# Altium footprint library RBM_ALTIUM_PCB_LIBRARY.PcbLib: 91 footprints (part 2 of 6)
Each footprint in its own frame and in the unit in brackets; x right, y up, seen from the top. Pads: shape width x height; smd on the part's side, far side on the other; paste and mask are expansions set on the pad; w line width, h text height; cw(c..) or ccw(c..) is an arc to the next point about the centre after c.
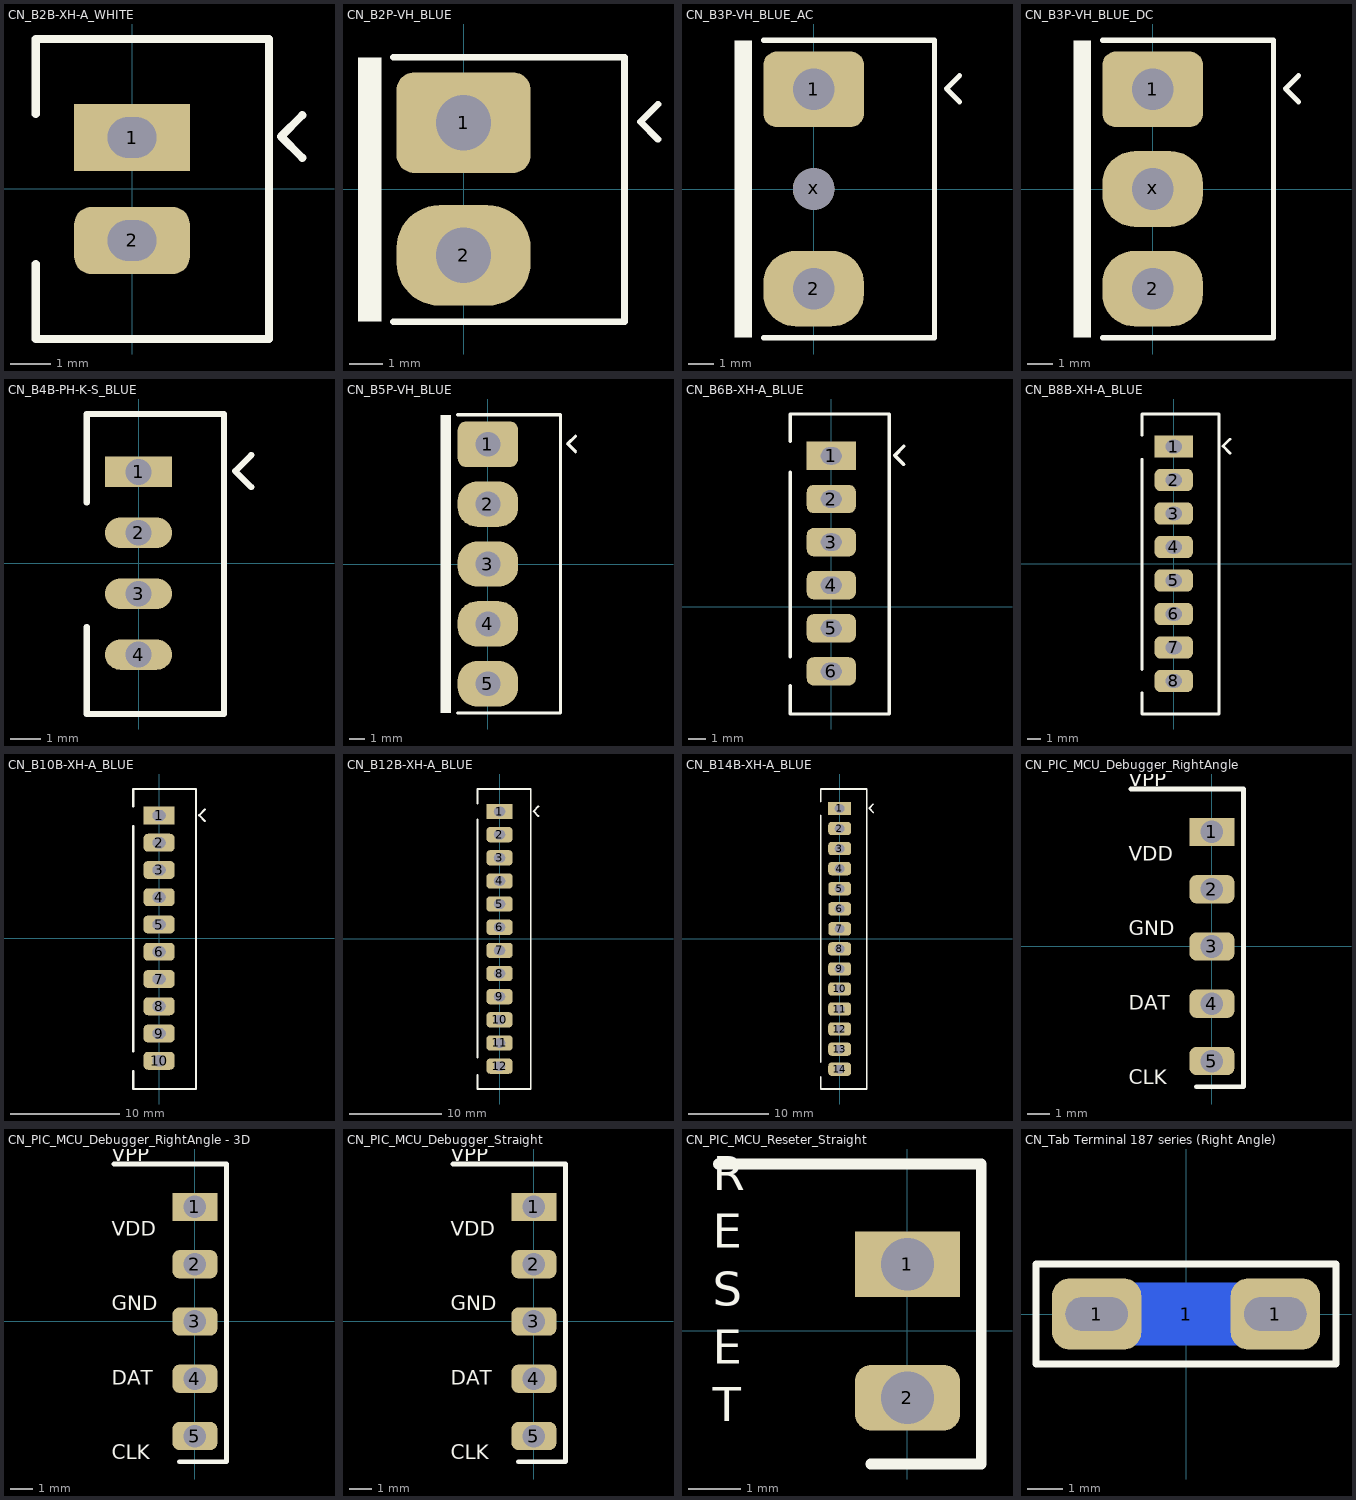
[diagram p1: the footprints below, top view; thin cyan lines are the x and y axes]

## CN_B2B-XH-A_WHITE [mm]
pads (2):
  rect 2.85x1.65 hole 1.2 slot 1 at 90 deg: 1(0,1.27)
  rrect50% 2.85x1.65 hole 1.2 slot 1 at 90 deg: 2(0,-1.27)
Top Overlay:
  lines w0.2: -2.375,-1.85 -2.375,-3.7 3.375,-3.7 3.375,3.7 -2.375,3.7 -2.375,1.85 ; 4.2,0.77 3.675,1.295 4.2,1.82
3D body "B2B-XH-A.STEP": height 7, standoff -3.4, extent -2.375,-3.7 3.375,3.7
3D body: height 7, standoff -3.5, extent -0.35,-1.615 0.35,-0.925
3D body: height 7, standoff -3.5, extent -0.35,0.925 0.35,1.615

## CN_B2P-VH_BLUE [mm] "3.96mm Pitch"
pads (2):
  rrect35% 4x3 hole 1.65: 1(0,1.98)
  rrect85% 4x3 hole 1.65: 2(0,-1.98)
Top Overlay:
  rectangle: -3.15,-3.96 -2.45,3.93
  lines w0.2: -2.1,-3.96 4.8,-3.96 4.8,3.93 -2.1,3.93 ; 5.8,1.48 5.275,2.005 5.8,2.53
3D body "B2P-VH.STEP": height 10.9, standoff -3.7, extent -3.75,-3.96 4.75,3.9

## CN_B3P-VH_BLUE_AC [mm] "3.96mm Pitch"
pads (3):
  rrect35% 4x3 / inner rect 4x2 / far side rect 4x2 hole 1.65: 1(0,3.96)
  rrect85% 4x3 hole 1.65: 2(0,-3.96)
  round 1.65 hole 1.65 unplated: x(0,0)
Top Overlay:
  rectangle: -3.15,-5.91 -2.45,5.91
  lines w0.2: -2,-5.91 4.8,-5.91 4.8,5.91 -2,5.91 ; 5.8,3.46 5.275,3.985 5.8,4.51
3D body "B3P-VH.STEP": height 10.9, standoff -3.7, extent -3.7,-5.91 4.8,5.91

## CN_B3P-VH_BLUE_DC [mm] "3.96mm Pitch"
pads (3):
  rrect35% 4x3 / inner rect 4x2 / far side rect 4x2 hole 1.65: 1(0,3.96)
  rrect85% 4x3 hole 1.65: 2(0,-3.96) x(0,0)
Top Overlay:
  rectangle: -3.15,-5.91 -2.45,5.91
  lines w0.2: -2,-5.91 4.8,-5.91 4.8,5.91 -2,5.91 ; 5.8,3.46 5.275,3.985 5.8,4.51
3D body "B3P-VH.STEP": height 10.9, standoff -3.7, extent -3.7,-5.91 4.8,5.91

## CN_B4B-PH-K-S_BLUE [mm] "Top Entry Header 2mm pitch 1X4pin  180° long"
pads (4):
  rect 2.2x1 hole 0.85: 1(0,3)
  oval 2.2x1 hole 0.85: 2(0,1) 3(0,-1) 4(0,-3)
Top Overlay:
  lines w0.2: -1.7,-2.1 -1.7,-4.95 2.8,-4.95 2.8,4.9 -1.7,4.9 -1.7,2 ; 3.7,2.5 3.175,3.025 3.7,3.55
3D body "B4B-PH-K-S.STEP": height 6, standoff -3.4, extent -1.7,-5 2.8,4.9

## CN_B5P-VH_BLUE [mm] "3.96mm Pitch"
pads (5):
  rrect35% 4x3 hole 1.65: 1(0,7.92)
  rrect85% 4x3 hole 1.65: 2(0,3.96) 3(0,0) 4(0,-3.96) 5(0,-7.92)
Top Overlay:
  rectangle: -3.15,-9.85 -2.45,9.87
  lines w0.2: -2,-9.85 4.8,-9.85 4.8,9.87 -2,9.87 ; 5.8,7.42 5.275,7.945 5.8,8.47
3D body "B5P-VH.STEP": height 10.9, standoff -3.7, extent -3.65,-9.85 4.85,9.89

## CN_B6B-XH-A_BLUE [mm] "2.5mm Pitch, 8pins, Top-Entry, XH Connector"
pads (6):
  rect 2.85x1.65 hole 1.2 slot 1 at 90 deg: 1(0,8.75)
  rrect50% 2.85x1.65 hole 1.2 slot 1 at 90 deg: 2(0,6.25) 3(0,3.75) 4(0,1.25) 5(0,-1.25) 6(0,-3.75)
Top Overlay:
  lines w0.2: -2.375,-6.22 3.375,-6.22 3.375,11.18 -2.375,11.18 -2.375,9.6 ; -2.375,-6.15 -2.375,-4.57 ; -2.375,-2.9 -2.375,7.8 ; 4.2,8.25 3.675,8.775 4.2,9.3
3D body "B6B-XH-A.STEP": height 7, standoff -3.4, extent -2.375,-6.22 3.375,11.18

## CN_B8B-XH-A_BLUE [mm] "2.5mm Pitch, 8pins, Top-Entry, XH Connector"
pads (8):
  rect 2.85x1.65 hole 1.2 slot 1 at 90 deg: 1(0,8.75)
  rrect50% 2.85x1.65 hole 1.2 slot 1 at 90 deg: 2(0,6.25) 3(0,3.75) 4(0,1.25) 5(0,-1.25) 6(0,-3.75) 7(0,-6.25) 8(0,-8.75)
Top Overlay:
  lines w0.2: -2.375,-9.64 -2.375,-11.22 3.375,-11.22 3.375,11.18 -2.375,11.18 -2.375,9.6 ; -2.375,-7.9 -2.375,7.8 ; 4.2,8.25 3.675,8.775 4.2,9.3
3D body "B8B-XH-A.STEP": height 7, standoff -3.4, extent -2.375,-11.22 3.375,11.18

## CN_B10B-XH-A_BLUE [mm] "2.5mmPitch, TopEntry, BlueColor, XH Connector"
pads (10):
  rect 2.85x1.65 hole 1.2 slot 1 at 90 deg: 1(0,11.25)
  rrect50% 2.85x1.65 hole 1.2 slot 1 at 90 deg: 2(0,8.75) 3(0,6.25) 4(0,3.75) 5(0,1.25) 6(0,-1.25) 7(0,-3.75) 8(0,-6.25) 9(0,-8.75) 10(0,-11.25)
Top Overlay:
  lines w0.2: -2.375,-12.2 -2.375,-13.84 3.375,-13.84 3.375,13.68 -2.375,13.68 -2.375,12.1 ; -2.375,-10.4 -2.375,10.3 ; 4.2,10.75 3.675,11.275 4.2,11.8
3D body "B10B-XH-A.STEP": height 7, standoff -3.4, extent -2.375,-13.72 3.375,13.68

## CN_B12B-XH-A_BLUE [mm] "2.5mmPitch, TopEntry, BlueColor, XH Connector"
pads (12):
  rect 2.85x1.65 hole 1.2 slot 1 at 90 deg: 1(0,13.75)
  rrect50% 2.85x1.65 hole 1.2 slot 1 at 90 deg: 2(0,11.25) 3(0,8.75) 4(0,6.25) 5(0,3.75) 6(0,1.25) 7(0,-1.25) 8(0,-3.75) 9(0,-6.25) 10(0,-8.75) 11(0,-11.25) 12(0,-13.75)
Top Overlay:
  lines w0.2: -2.375,-14.7 -2.375,-16.22 3.375,-16.22 3.375,16.18 -2.375,16.18 -2.375,14.6 ; -2.375,-12.8 -2.375,12.9 ; 4.2,13.25 3.675,13.775 4.2,14.3
3D body "B12B-XH-A.STEP": height 7, standoff -3.4, extent -2.375,-16.22 3.375,16.18

## CN_B14B-XH-A_BLUE [mm] "2.5mmPitch, TopEntry, BlueColor, XH Connector"
pads (14):
  rect 2.85x1.65 hole 1.2 slot 1 at 90 deg: 1(0,16.25)
  rrect50% 2.85x1.65 hole 1.2 slot 1 at 90 deg: 2(0,13.75) 3(0,11.25) 4(0,8.75) 5(0,6.25) 6(0,3.75) 7(0,1.25) 8(0,-1.25) 9(0,-3.75) 10(0,-6.25) 11(0,-8.75) 12(0,-11.25) 13(0,-13.75) 14(0,-16.25)
Top Overlay:
  lines w0.2: -2.375,-17.2 -2.375,-18.72 3.375,-18.72 3.375,18.68 -2.375,18.68 -2.375,17.1 ; -2.375,-15.4 -2.375,15.4 ; 4.2,15.75 3.675,16.275 4.2,16.8
3D body "B14B-XH-A.STEP": height 7, standoff -3.4, extent -2.375,-18.72 3.375,18.68

## CN_PIC_MCU_Debugger_RightAngle [mm] "2.54mmPitch, 5pins, StraightType, Male Connector"
pads (5):
  rect 2x1.25 hole 1: 1(0,5.08)
  rrect50% 2x1.25 hole 1: 2(0,2.54) 3(0,0) 4(0,-2.54) 5(0,-5.08)
Top Overlay:
  lines w0.203: -3.6,6.985 1.4,6.985 1.4,-6.22 -0.7,-6.22
  text "VPP /  /  / VDD /  /  / GND /  /  / DAT /  /  / CLK" at -3.7,-6.32 h1.1
Bottom Overlay:
  lines w0.203: -3.6,6.98 1.4,6.98 1.4,-6.225 -0.7,-6.225
  text "VPP /  /  / VDD /  /  / GND /  /  / DAT /  /  / CLK" at -1.3,-6.32 h1.1

## CN_PIC_MCU_Debugger_RightAngle - 3D [mm] "2.54mmPitch, 5pins, StraightType, Male Connector"
pads (5):
  rect 2x1.25 hole 1: 1(0,5.08)
  rrect50% 2x1.25 hole 1: 2(0,2.54) 3(0,0) 4(0,-2.54) 5(0,-5.08)
Top Overlay:
  lines w0.203: -3.6,6.985 1.4,6.985 1.4,-6.22 -0.7,-6.22
  text "VPP /  /  / VDD /  /  / GND /  /  / DAT /  /  / CLK" at -3.7,-6.32 h1.1
Bottom Overlay:
  lines w0.203: -3.6,6.98 1.4,6.98 1.4,-6.225 -0.7,-6.225
  text "VPP /  /  / VDD /  /  / GND /  /  / DAT /  /  / CLK" at -1.3,-6.32 h1.1
3D body "5-Way 2.54mm Right Angle Male Header.STEP": height 2.51, standoff -3, extent -0.365,-6.32 9.765,6.38

## CN_PIC_MCU_Debugger_Straight [mm] "2.54mmPitch, 5pins, StraightType, Male Connector"
pads (5):
  rect 2x1.25 hole 1: 1(0,5.08)
  rrect50% 2x1.25 hole 1: 2(0,2.54) 3(0,0) 4(0,-2.54) 5(0,-5.08)
Top Overlay:
  lines w0.203: -3.6,6.985 1.4,6.985 1.4,-6.22 -0.7,-6.22
  text "VPP /  /  / VDD /  /  / GND /  /  / DAT /  /  / CLK" at -3.7,-6.32 h1.1
Bottom Overlay:
  lines w0.203: -3.6,6.98 1.4,6.98 1.4,-6.225 -0.7,-6.225
  text "VPP /  /  / VDD /  /  / GND /  /  / DAT /  /  / CLK" at -1.3,-6.32 h1.1
3D body "5Pins 2.54mm Male Header.STEP": height 8.54, standoff -3, extent -1.245,-6.35 1.245,6.35

## CN_PIC_MCU_Reseter_Straight [mm] "2.54mmPitch, 2pins, StraightType, Male Connector"
pads (2):
  rect 2x1.25 hole 1: 1(0,1.27)
  rrect50% 2x1.25 hole 1: 2(0,-1.27)
Top Overlay:
  lines w0.203: -3.6,3.175 1.4,3.175 1.4,-2.53 -0.7,-2.53
  text "R / E / S / E / T" at -3.7,-1.93 h1.1
Bottom Overlay:
  lines w0.203: -3.6,3.17 1.4,3.17 1.4,-2.53 -0.7,-2.53
  text "R / E / S / E / T" at -1.3,-1.93 h1.1
3D body "User Library-Header_Male_2Pin.STEP": height 8.54, standoff -3, extent -1.245,-2.54 1.245,2.54

## CN_Tab Terminal 187 series (Right Angle) [mm]
pads (3):
  rrect50% 2.5x2 hole 0.95 slot 1.75 at 0 deg: 1(-2.5,0) 1(2.5,0)
  rect 2.85x1.75 smd far side: 1(0,0)
Top Overlay:
  lines w0.2: -4.2,-1.397 4.2,-1.397 4.2,1.397 -4.2,1.397 -4.2,-1.397
3D body "4.8mm PCB Tab Terminal (Right Angle).stp": height 9.3, standoff -3.7, extent -3.3,-0.4 9.5,0.4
